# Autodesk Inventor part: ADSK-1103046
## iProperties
Shininess: 50.0
Length Units: 11272
Angle Units: 11279
Time Units: 11290
Mass Units: 11286
Length Display Precision: 4
Angle Display Precision: 2
Compacted: True
Created: 2000-07
Part Number: ADSK-1103046
Document SubType Name: Modeling
Description: ENGINE COVER - REAR
Mass: 4.64243 g
Surface Area: 23.1415 cm^2
Volume: 1.71307 cm^3
Density: 2.71 g/cm^3
Material: Aluminum-6061
Density: 0.0
Volumn: 0.0
Area: 0.0
PropertySet Name: Model Information
Control State: 0
Master: False
Checked Out: False
Author: Autodesk, Inc.
